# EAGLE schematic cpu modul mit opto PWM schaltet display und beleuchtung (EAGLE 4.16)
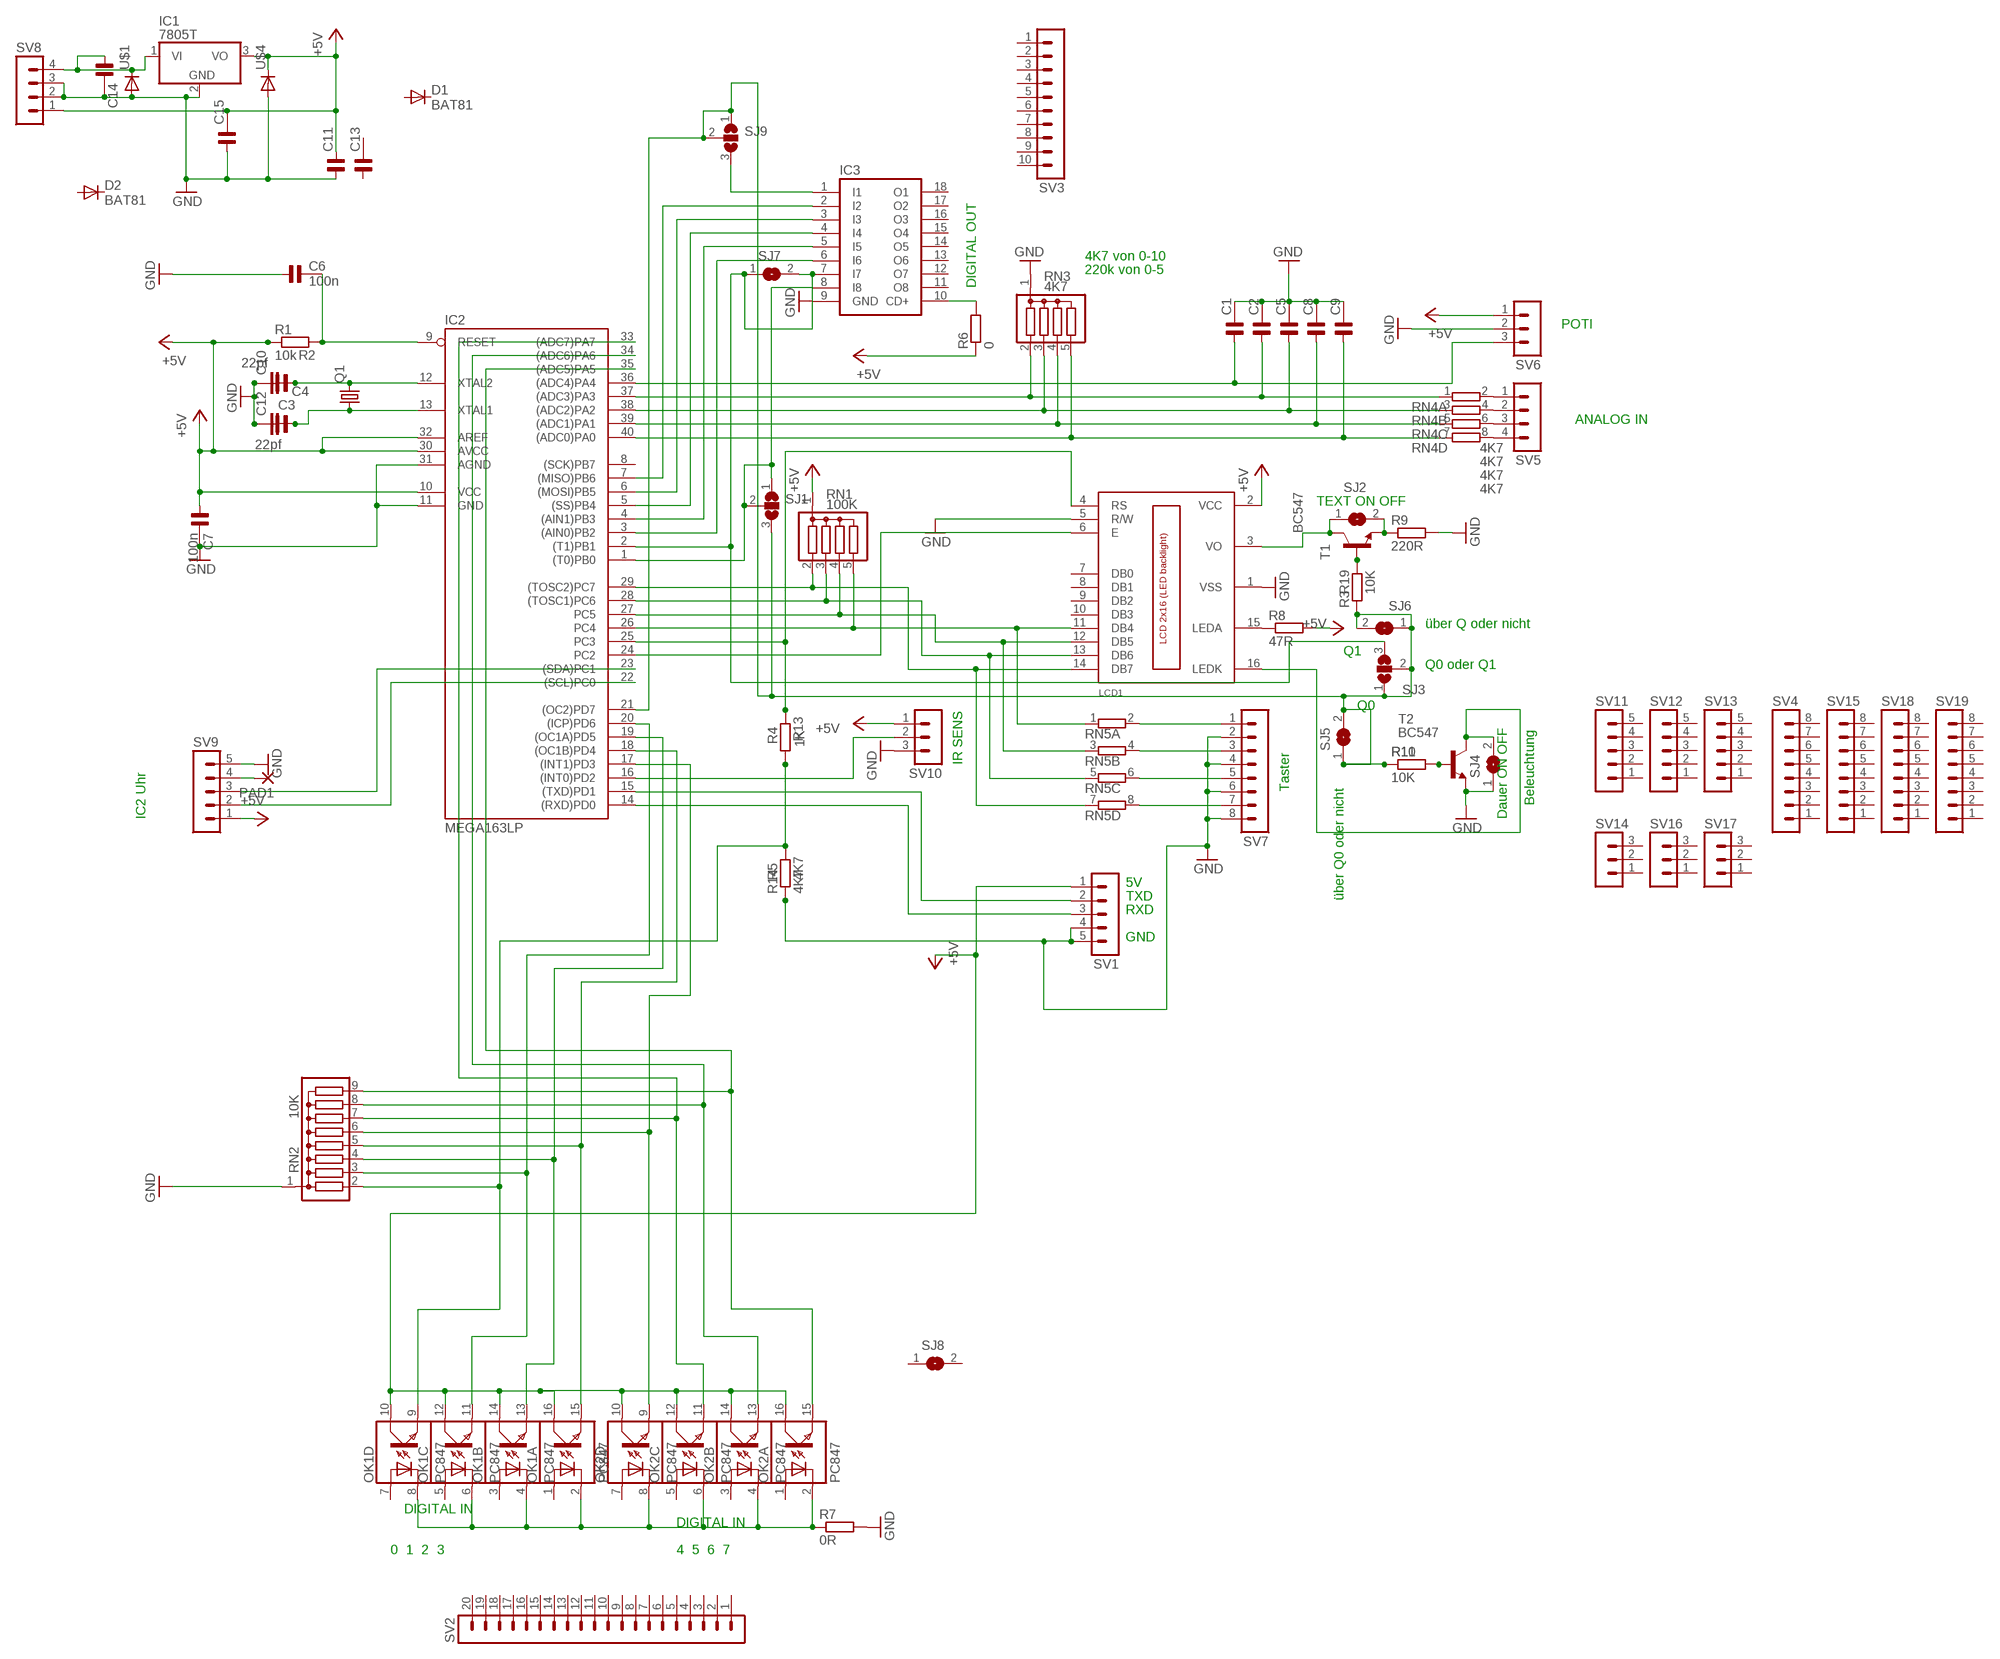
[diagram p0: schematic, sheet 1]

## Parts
C1  C-2.5-5/2  [C2.5/5-2]
C2  C-2.5-5/2  [C2.5/5-2]
C3  22pf  C-2.5-5/2  [C2.5/5-2]
C4  22pf  C-2.5-5/2  [C2.5/5-2]
C5  C-2.5-5/2  [C2.5/5-2]
C6  100n  C-2.5-5/4  [C2.5/5-4]
C7  100n  C-2.5-5/4  [C2.5/5-4]
C8  C-2.5-5/2  [C2.5/5-2]
C9  C-2.5-5/2  [C2.5/5-2]
C10  C-EUC1005  [C1005]
C11  C7.5/6  [C7.5B6]
C12  C-EUC1005  [C1005]
C13  C-2.5-5/5  [C2.5/5-5]
C14  C-2.5-5/5  [C2.5/5-5]
C15  C-2.5-5/5  [C2.5/5-5]
D1  BAT81  [DO34-7]
D2  BAT81  [DO34-7]
IC1  7805T  [TO220H]
IC2  MEGA163LP  [DIL40]
IC3  ULN2803A  [DIL18]
LCD1  LCD_2X16  [HY-1602F]
OK1  PC847  [DIL16]
OK2  PC847  [DIL16]
PAD1  1,6/0,8  [1,6/0,8]
Q1  HC49/S  [HC49/S]
R1  10k  R-EU_R1206  [R1206]
R2  R-EU_0207/10  [0207/10]
R3  R-EU_0207/10  [0207/10]
R4  R-EU_0207/10  [0207/10]
R5  4K7  R-EU_0207/10  [0207/10]
R6  0  R-EU_0207/10  [0207/10]
R7  0R  R-EU_0207/10  [0207/10]
R8  47R  R-EU_0207/10  [0207/10]
R9  220R  R-EU_0207/10  [0207/10]
R10  R-EU_M1206  [M1206]
R11  10K  R-EU_0207/10  [0207/10]
R13  1K  R-EU_R1206  [R1206]
R14  4K7  R-EU_R1206  [R1206]
R19  10K  R-EU_R1206  [R1206]
RN1  100K  G04R  [SIL5]
RN2  10K  G08R  [SIL9]
RN3  4K7  G04R  [SIL5]
RN4  4K7  E4R  [SIL8]
RN5  E4R  [SIL8]
SJ1  SJ2W  [SJ_2]
SJ2  SJ  [SJ]
SJ3  SJ2W  [SJ_2]
SJ4  SJ  [SJ]
SJ5  SJ  [SJ]
SJ6  SJ  [SJ]
SJ7  SJ  [SJ]
SJ8  SJ  [SJ]
SJ9  SJ2W  [SJ_2]
SV1  MA05-1  [MA05-1]
SV2  MA20-1  [MA20-1]
SV3  MA10-1  [MA10-1]
SV4  MA08-1  [MA08-1]
SV5  MA04-1  [MA04-1]
SV6  MA03-1  [MA03-1]
SV7  MA08-1  [MA08-1]
SV8  MA04-1  [MA04-1]
SV9  MA05-1  [MA05-1]
SV10  MA03-1  [MA03-1]
SV11  MA05-1  [MA05-1]
SV12  MA05-1  [MA05-1]
SV13  MA05-1  [MA05-1]
SV14  MA03-1  [MA03-1]
SV15  MA08-1  [MA08-1]
SV16  MA03-1  [MA03-1]
SV17  MA03-1  [MA03-1]
SV18  MA08-1  [MA08-1]
SV19  MA08-1  [MA08-1]
T1  BC547  [TO92]
T2  BC547  [TO92]
U$1  DIODE-SMB  [SMB]
U$4  DIODE-SMB  [SMB]

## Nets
GND: C1.3 C2.3 C5.3 C8.3 C9.3
N$1: C4.1 C10.1 IC2.12(XTAL2) Q1.2
N$2: C6.3 IC2.9(RESET) R1.2 R2.1
N$3: C3.1 C12.1 IC2.13(XTAL1) Q1.1
N$4: IC2.33((ADC7)PA7) OK2.11(C:EMIT) RN2.7
N$5: R9.1 SJ2.2 T1.1(E)
N$6: IC2.34((ADC6)PA6) OK2.13(B:EMIT) RN2.8
N$7: IC2.29((TOSC2)PC7) LCD1.14(DB7) RN1.2 RN5.7
N$8: IC2.28((TOSC1)PC6) LCD1.13(DB6) RN1.3 RN5.5
N$9: IC2.27(PC5) LCD1.12(DB5) RN1.4 RN5.3
N$10: IC2.26(PC4) LCD1.11(DB4) RN1.5 RN5.1
N$11: LCD1.15(LEDA) R8.1
N$12: LCD1.3(VO) SJ2.1 T1.3(C)
N$13: IC2.2((T1)PB1) IC3.7(I7) SJ3.3 SJ7.1 SJ7.2
N$14: IC2.24(PC2) LCD1.6(E)
N$15: R3.2 R19.2 T1.2(B)
N$17: OK1.9(D:EMIT) R4.1 R5.2 R13.2 R14.2 RN2.2
N$18: IC2.3((AIN0)PB2) IC3.6(I6)
N$19: IC2.14((RXD)PD0) SV1.3
N$20: IC2.4((AIN1)PB3) IC3.5(I5)
N$21: IC2.35((ADC5)PA5) OK2.15(A:EMIT) RN2.9
N$22: IC2.15((TXD)PD1) SV1.2
N$25: IC2.5((SS)PB4) IC3.4(I4)
N$26: IC2.6((MOSI)PB5) IC3.3(I3)
N$27: IC2.7((MISO)PB6) IC3.2(I2)
N$31: IC2.17((INT1)PD3) OK2.9(D:EMIT) RN2.6
N$32: C9.1 IC2.40((ADC0)PA0) RN3.5 RN4.7
N$33: C8.1 IC2.39((ADC1)PA1) RN3.4 RN4.5
N$34: C5.1 IC2.38((ADC2)PA2) RN3.3 RN4.3
N$35: C2.1 IC2.37((ADC3)PA3) RN3.2 RN4.1
N$36: C1.1 IC2.36((ADC4)PA4) SV6.3
N$37: RN4.2 SV5.1
N$38: RN4.4 SV5.2
N$39: RN4.6 SV5.3
N$40: RN4.8 SV5.4
N$41: RN5.2 SV7.1
N$42: RN5.4 SV7.3
N$43: RN5.6 SV7.5
N$44: RN5.8 SV7.7
N$45: C14.1 IC1.1(VI) SV8.4 U$1.C
N$46: IC2.23((SDA)PC1) SV9.3
N$47: IC2.22((SCL)PC0) SV9.2
N$48: IC2.25(PC3) LCD1.4(RS) R4.2 R13.1
N$49: PAD1.1(P) SV9.4
N$50: IC2.16((INT0)PD2) SV10.2
N$67: IC2.20((ICP)PD6) OK1.11(C:EMIT) RN2.3
N$103: IC2.21((OC2)PD7) R3.1 R10.1 R11.1 R19.1 SJ1.3 SJ3.1 SJ3.2 SJ5.1 SJ5.2 SJ6.1 SJ6.2 SJ9.1 SJ9.2
N$208: IC2.18((OC1B)PD4) OK1.15(A:EMIT) RN2.5
N$209: IC2.19((OC1A)PD5) OK1.13(B:EMIT) RN2.4
N$210: IC3.10(CD+) R6.2
N$211: OK1.2(A:C) OK1.4(B:C) OK1.6(C:C) OK1.8(D:C) OK2.2(A:C) OK2.4(B:C) OK2.6(C:C) OK2.8(D:C) R7.1
N$238: R10.2 R11.2 T2.2(B)
N$239: LCD1.16(LEDK) SJ4.2 T2.3(C)
N$265: IC3.1(I1) SJ9.3
N$266: IC2.1((T0)PB0) IC3.8(I8) SJ1.1 SJ1.2
N$371: C7.1 C11.2 C15.3 IC1.3(VO) IC2.10(VCC) IC2.30(AVCC) IC2.32(AREF) LCD1.2(VCC) OK1.10(D:COL) OK1.12(C:COL) OK1.14(B:COL) OK1.16(A:COL) OK2.10(D:COL) OK2.12(C:COL) OK2.14(B:COL) OK2.16(A:COL) R1.1 R2.2 R6.1 R8.2 RN1.1 SV1.1 SV6.1 SV8.1 SV9.1 SV10.1 U$4.C ; supply symbol labelled +5V
N$373: C3.3 C4.3 C6.1 C7.3 C10.2 C11.1 C12.2 C14.3 C15.1 IC1.2(GND) IC2.11(GND) IC2.31(AGND) IC3.9(GND) LCD1.1(VSS) LCD1.5(R/W) R5.1 R7.2 R9.2 R14.1 RN2.1 RN3.1 SJ4.1 SV1.4 SV1.5 SV6.2 SV7.2 SV7.4 SV7.6 SV7.8 SV8.2 SV8.3 SV9.5 SV10.3 T2.1(E) U$1.A U$4.A ; supply symbol labelled GND
Unconnected: C1.2 C2.2 C3.2 C4.2 C5.2 C6.2 C7.2 C8.2 C9.2 C13.1 C13.2 C13.3 C14.2 C15.2 D1.A D1.C D2.A D2.C IC2.8((SCK)PB7) IC3.11(O8) IC3.12(O7) IC3.13(O6) IC3.14(O5) IC3.15(O4) IC3.16(O3) IC3.17(O2) IC3.18(O1) LCD1.7(DB0) LCD1.8(DB1) LCD1.9(DB2) LCD1.10(DB3) OK1.1(A:A) OK1.3(B:A) OK1.5(C:A) OK1.7(D:A) OK2.1(A:A) OK2.3(B:A) OK2.5(C:A) OK2.7(D:A) SJ8.1 SJ8.2 SV2.1 SV2.2 SV2.3 SV2.4 SV2.5 SV2.6 SV2.7 SV2.8 SV2.9 SV2.10 SV2.11 SV2.12 SV2.13 SV2.14 SV2.15 SV2.16 SV2.17 SV2.18 SV2.19 SV2.20 SV3.1 SV3.2 SV3.3 SV3.4 SV3.5 SV3.6 SV3.7 SV3.8 SV3.9 SV3.10 SV4.1 SV4.2 SV4.3 SV4.4 SV4.5 SV4.6 SV4.7 SV4.8 SV11.1 SV11.2 SV11.3 SV11.4 SV11.5 SV12.1 SV12.2 SV12.3 SV12.4 SV12.5 SV13.1 SV13.2 SV13.3 SV13.4 SV13.5 SV14.1 SV14.2 SV14.3 SV15.1 SV15.2 SV15.3 SV15.4 SV15.5 SV15.6 SV15.7 SV15.8 SV16.1 SV16.2 SV16.3 SV17.1 SV17.2 SV17.3 SV18.1 SV18.2 SV18.3 SV18.4 SV18.5 SV18.6 SV18.7 SV18.8 SV19.1 SV19.2 SV19.3 SV19.4 SV19.5 SV19.6 SV19.7 SV19.8

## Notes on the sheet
- 4K7 von 0-10
- 220k von 0-5
- DIGITAL OUT
- POTI
- ANALOG IN
- TEXT ON OFF
- über Q oder nicht
- Q1
- Q0 oder Q1
- Q0
- IR SENS
- Taster
- Beleuchtung
- IC2 Uhr | Dauer ON OFF
- 5V
- TXD | über Q0 oder nicht
- RXD
- GND
- DIGITAL IN
- DIGITAL IN
- 0  1  2  3 | 4  5  6  7

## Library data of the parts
C1-C9 C13-C15 = capacitor-wima:C-: CAPACITOR for alternative placement naming: default grid - extended grid/package width
C10 C12 = rcl:C-EU: CAPACITOR, European symbol
C11 = capacitor-wima:C: CAPACITOR
D1 D2 = diode:BAT81: DIODE
IC1 = linear:78*: Positive VOLTAGE REGULATOR
IC2 = atmel:MEGA163*P: MICROCONTROLLER 16 Kbytes FLASH, 1 Kbytes EEPROM 1 Kbytes SRAM UART 8-channel 10 bit ADC hardware multiplier
IC3 = uln-udn:ULN2803A: DRIVER ARRAY
LCD1 = lcd_2x16_led_backlight:LCD_2X16
OK1 OK2 = optocoupler:PC847: SHARP OPTO COUPLER
PAD1 = wirepad:1,6/0,8: THROUGH-HOLE PAD
Q1 = crystal:HC49/S: CRYSTAL
R1-R11 R13 R14 R19 = rcl:R-EU_: RESISTOR, European symbol
RN1 RN3 = resistor-sil:G04R: SIL RESISTOR
RN2 = resistor-sil:G08R: SIL RESISTOR
RN4 RN5 = resistor-sil:E4R: SIL RESISTOR
SJ1 SJ3 SJ9 = jumper:SJ2W: SMD solder JUMPER
SJ2 SJ4-SJ8 = jumper:SJ: SMD solder JUMPER
SV1 SV9 SV11-SV13 = con-lstb:MA05-1: PIN HEADER
SV2 = con-lstb:MA20-1: PIN HEADER
SV3 = con-lstb:MA10-1: PIN HEADER
SV4 SV7 SV15 SV18 SV19 = con-lstb:MA08-1: PIN HEADER
SV5 SV8 = con-lstb:MA04-1: PIN HEADER
SV6 SV10 SV14 SV16 SV17 = con-lstb:MA03-1: PIN HEADER
T1 T2 = transistor-npn:BC547: NPN TRANSISTOR
U$1 U$4 = diode:DIODE-: DIODE

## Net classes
0 default: width 0.406 mm, drill 0.254 mm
